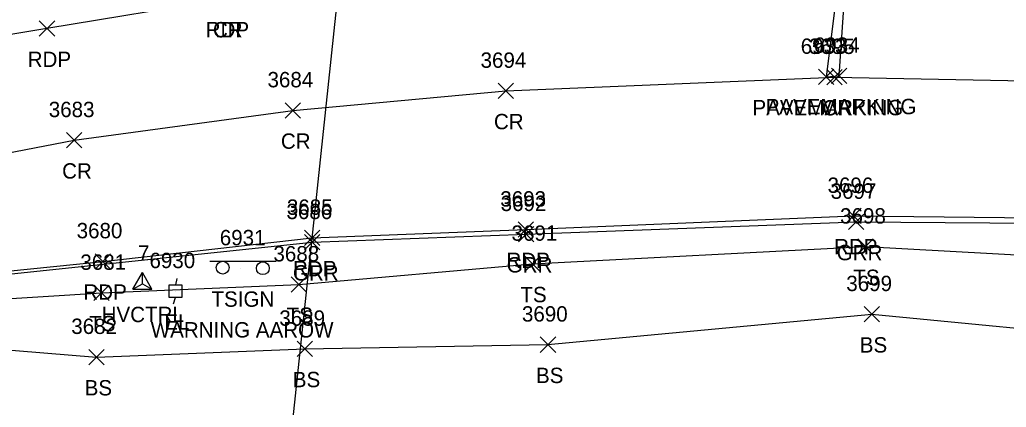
# Model space of a CAD drawing. Extents: x 1505656 to 1508446, y 700805 to 703031.
# Drawn here: x 1506576.4 to 1506704.7, y 701784.4 to 701834.8 of the extents above; entities that cross this region are included whole.
import ezdxf

# ---------------------------------------------------------------- set-up
doc = ezdxf.new("R2010")
doc.units = 0
for name, color, linetype in [('C_A', 7, 'Continuous'), ('C_I', 7, 'Continuous'), ('CPSM', 7, 'Continuous'), ('DDEFAULT', 7, 'Continuous'), ('L_A', 7, 'Continuous'), ('L_I', 7, 'Continuous'), ('L_TIC', 7, 'Continuous'), ('LELB', 7, 'Continuous'), ('P_A', 7, 'Continuous'), ('P_I', 7, 'Continuous'), ('P_TIC', 7, 'Continuous'), ('PET', 7, 'Continuous'), ('PRC', 7, 'Continuous'), ('R_A', 7, 'Continuous'), ('R_I', 7, 'Continuous'), ('R_TIC', 7, 'Continuous'), ('RGR', 7, 'Continuous'), ('S_A', 7, 'Continuous'), ('S_C', 7, 'Continuous'), ('S_I', 7, 'Continuous'), ('S_TIC', 7, 'Continuous'), ('SSGN', 7, 'Continuous'), ('STS', 7, 'Continuous'), ('U_A', 7, 'Continuous'), ('U_I', 7, 'Continuous'), ('UEPT', 7, 'Continuous')]:
    doc.layers.add(name, color=color, linetype=linetype)

msp = doc.modelspace()

# ---------------------------------------------------------------- linework, layer by layer
at = {"layer": 'CPSM'}
for p, q in [((1506591.08, 701799.76), (1506592.33, 701801.92)), ((1506593.58, 701799.76), (1506592.33, 701801.92)), ((1506592.33, 701800.48), (1506592.33, 701801.92)), ((1506591.08, 701799.76), (1506592.33, 701800.48)), ((1506592.33, 701800.48), (1506592.33, 701800.48)), ((1506592.33, 701800.48), (1506593.58, 701799.76)), ((1506591.08, 701799.76), (1506593.58, 701799.76))]:
    msp.add_line(p, q, dxfattribs=at)
at = {"layer": 'DDEFAULT'}
msp.add_lwpolyline([(1506607.79, 701743.71), (1506620.07, 701859.63)], dxfattribs=at)
at = {"layer": 'L_TIC'}
for points in [[(1506685.41, 701804.31), (1506687.41, 701806.31)], [(1506687.41, 701804.31), (1506685.41, 701806.31)], [(1506642.1, 701802.07), (1506644.1, 701804.07)], [(1506644.1, 701802.07), (1506642.1, 701804.07)], [(1506611.69, 701799.38), (1506613.69, 701801.38)], [(1506613.69, 701799.38), (1506611.69, 701801.38)], [(1506586.01, 701798.29), (1506588.01, 701800.29)], [(1506588.01, 701798.29), (1506586.01, 701800.29)], [(1506686.22, 701795.52), (1506688.22, 701797.52)], [(1506688.22, 701795.52), (1506686.22, 701797.52)], [(1506612.46, 701791.01), (1506614.46, 701793.01)], [(1506614.46, 701791.01), (1506612.46, 701793.01)], [(1506644.1, 701791.55), (1506646.1, 701793.55)], [(1506646.1, 701791.55), (1506644.1, 701793.55)], [(1506585.38, 701789.94), (1506587.38, 701791.94)], [(1506587.38, 701789.94), (1506585.38, 701791.94)]]:
    msp.add_lwpolyline(points, dxfattribs=at)
at = {"layer": 'LELB'}
for points in [[(1506551.26, 701797.2), (1506558.65, 701795.18), (1506571.81, 701798.33), (1506587.01, 701799.29), (1506612.69, 701800.38), (1506643.1, 701803.07), (1506686.41, 701805.31), (1506719.43, 701803.51), (1506758.52, 701801.61), (1506800.37, 701797.23), (1506837.5, 701789.66)], [(1506558.65, 701795.18), (1506572.61, 701792.03), (1506586.38, 701790.94), (1506613.46, 701792.01), (1506645.1, 701792.55), (1506687.22, 701796.52), (1506721.34, 701793.21), (1506758.89, 701789.89), (1506799.48, 701793.76), (1506835.55, 701784.17), (1506872.57, 701779.99)]]:
    msp.add_lwpolyline(points, dxfattribs=at)
at = {"layer": 'P_TIC'}
for points in [[(1506578.92, 701832.68), (1506580.92, 701834.68)], [(1506580.92, 701832.68), (1506578.92, 701834.68)], [(1506681.36, 701826.38), (1506683.36, 701828.38)], [(1506683.36, 701826.38), (1506681.36, 701828.38)], [(1506638.63, 701824.58), (1506640.63, 701826.58)], [(1506640.63, 701824.58), (1506638.63, 701826.58)], [(1506610.92, 701822.04), (1506612.92, 701824.04)], [(1506612.92, 701822.04), (1506610.92, 701824.04)], [(1506582.46, 701818.16), (1506584.46, 701820.16)], [(1506584.46, 701818.16), (1506582.46, 701820.16)], [(1506683.84, 701808.3), (1506685.84, 701810.3)], [(1506685.84, 701808.3), (1506683.84, 701810.3)], [(1506641.2, 701806.52), (1506643.2, 701808.52)], [(1506643.2, 701806.52), (1506641.2, 701808.52)], [(1506613.43, 701805.45), (1506615.43, 701807.45)], [(1506615.43, 701805.45), (1506613.43, 701807.45)], [(1506586.17, 701802.39), (1506588.17, 701804.39)], [(1506588.17, 701802.39), (1506586.17, 701804.39)]]:
    msp.add_lwpolyline(points, dxfattribs=at)
at = {"layer": 'PET'}
for points in [[(1506503.96, 701935.54), (1506531.72, 701909.61), (1506554.95, 701887), (1506562.54, 701879.07), (1506567.48, 701868.84), (1506568.91, 701854.51), (1506562.93, 701840.15), (1506555.32, 701831.94), (1506552.83, 701829.17), (1506534.04, 701823.97), (1506542.56, 701811.26), (1506550.99, 701798.42), (1506571.31, 701801.75), (1506587.17, 701803.39), (1506614.43, 701806.45), (1506642.2, 701807.52), (1506684.84, 701809.3), (1506720.17, 701808.92), (1506758.85, 701806.5), (1506801.05, 701801.39), (1506837.91, 701794.78)], [(1506681.03, 701845.6), (1506644.05, 701842.71), (1506621.37, 701840), (1506603.08, 701837.54), (1506579.92, 701833.68), (1506552.83, 701829.17)]]:
    msp.add_lwpolyline(points, dxfattribs=at)
at = {"layer": 'PRC'}
msp.add_lwpolyline([(1506542.56, 701811.26), (1506583.46, 701819.16), (1506611.92, 701823.04), (1506639.63, 701825.58), (1506682.36, 701827.38), (1506720.71, 701826.61), (1506759.11, 701825.09), (1506802.87, 701820.09), (1506841.69, 701813.28), (1506883.62, 701802.65), (1506939.52, 701784.02), (1506961.71, 701775.32), (1506990.86, 701762.61), (1507014.94, 701750.7), (1507047.18, 701733.31), (1507059.63, 701726.12), (1507093.71, 701705.34), (1507109.29, 701695.3), (1507149.33, 701669.46), (1507158.78, 701662.65), (1507185.01, 701645.13), (1507221.62, 701620.55), (1507265.06, 701591.23)], dxfattribs=at)
at = {"layer": 'R_TIC'}
for points in [[(1506684.18, 701807.53), (1506686.18, 701809.53)], [(1506686.18, 701807.53), (1506684.18, 701809.53)], [(1506613.43, 701804.89), (1506615.43, 701806.89)], [(1506615.43, 701804.89), (1506613.43, 701806.89)], [(1506641.25, 701805.94), (1506643.25, 701807.94)], [(1506643.25, 701805.94), (1506641.25, 701807.94)]]:
    msp.add_lwpolyline(points, dxfattribs=at)
at = {"layer": 'RGR'}
msp.add_lwpolyline([(1506551.24, 701797.84), (1506571.59, 701801.36), (1506614.43, 701805.89), (1506642.25, 701806.94), (1506685.18, 701808.53), (1506719.99, 701808.29), (1506758.76, 701805.83), (1506800.88, 701800.84), (1506837.73, 701793.83), (1506878.73, 701783.93), (1506932.12, 701767.5), (1506956.3, 701757.77), (1506981.82, 701746.54), (1507005.68, 701734.48), (1507036.84, 701717.62), (1507049.28, 701710.58), (1507081.07, 701691.67), (1507098.39, 701680.19), (1507136.76, 701655.28), (1507148.64, 701647.4), (1507175.49, 701629.55), (1507209.72, 701606.66), (1507254.7, 701574.39), (1507264.03, 701565.84)], dxfattribs=at)
at = {"layer": 'S_TIC'}
for points in [[(1506680.28, 701826.4), (1506682.28, 701828.4)], [(1506682.28, 701826.4), (1506680.28, 701828.4)], [(1506681.99, 701826.54), (1506683.99, 701828.54)], [(1506683.99, 701826.54), (1506681.99, 701828.54)]]:
    msp.add_lwpolyline(points, dxfattribs=at)
at = {"layer": 'SSGN'}
for p, q in [((1506601.12, 701803.4), (1506609.72, 701803.4)), ((1506605.15, 701802.5), (1506605.15, 701802.5))]:
    msp.add_line(p, q, dxfattribs=at)
for centre in [(1506602.78, 701802.57), (1506608, 701802.5)]:
    msp.add_circle(centre, 0.833, dxfattribs=at)
at = {"layer": 'STS'}
msp.add_lwpolyline([(1506683.55, 701845.4), (1506681.28, 701827.4), (1506682.99, 701827.54), (1506684.23, 701845.91)], dxfattribs=at)
at = {"layer": 'UEPT'}
for p, q in [((1506595.81, 701798.68), (1506595.81, 701800.35)), ((1506595.81, 701800.35), (1506597.48, 701800.35)), ((1506596.81, 701801.18), (1506596.64, 701800.35)), ((1506597.48, 701800.35), (1506597.48, 701798.68)), ((1506596.64, 701799.51), (1506596.64, 701799.51)), ((1506597.48, 701798.68), (1506595.81, 701798.68)), ((1506596.39, 701797.85), (1506596.64, 701798.68))]:
    msp.add_line(p, q, dxfattribs=at)

# ---------------------------------------------------------------- texts
at = {"layer": 'C_A'}
msp.add_text('HVCTRL', height=2, dxfattribs=at).set_placement((1506587.03, 701795.48))
at = {"layer": 'C_I'}
msp.add_text('7', height=2, dxfattribs=at).set_placement((1506591.77, 701803.48))
at = {"layer": 'L_A'}
for s, p in [('TS', (1506684.82, 701800.31)), ('TS', (1506641.51, 701798.07)), ('TS', (1506611.1, 701795.38)), ('TS', (1506585.41, 701794.29)), ('BS', (1506685.66, 701791.52)), ('BS', (1506611.9, 701787.01)), ('BS', (1506643.54, 701787.55)), ('BS', (1506584.82, 701785.94))]:
    msp.add_text(s, height=2, dxfattribs=at).set_placement(p)
at = {"layer": 'L_I'}
for s, p in [('3698', (1506683.1, 701808.31)), ('3691', (1506640.36, 701806.07)), ('3681', (1506584.26, 701802.29)), ('3688', (1506609.38, 701803.38)), ('3699', (1506683.91, 701799.52)), ('3689', (1506610.15, 701795.01)), ('3690', (1506641.71, 701795.55)), ('3682', (1506583.08, 701793.94))]:
    msp.add_text(s, height=2, dxfattribs=at).set_placement(p)
at = {"layer": 'P_A'}
for s, p in [('RDP', (1506600.57, 701832.54)), ('CR', (1506601.51, 701832.54)), ('RDP', (1506577.41, 701828.68)), ('CR', (1506680.79, 701822.38)), ('CR', (1506638.07, 701820.58)), ('CR', (1506610.35, 701818.04)), ('CR', (1506581.89, 701814.16)), ('RDP', (1506682.32, 701804.3)), ('RDP', (1506639.69, 701802.52)), ('RDP', (1506611.92, 701801.45)), ('RDP', (1506584.66, 701798.39))]:
    msp.add_text(s, height=2, dxfattribs=at).set_placement(p)
at = {"layer": 'P_I'}
for s, p in [('3695', (1506679.05, 701830.38)), ('3694', (1506636.33, 701828.58)), ('3684', (1506608.61, 701826.04)), ('3683', (1506580.15, 701822.16)), ('3696', (1506681.47, 701812.3)), ('3693', (1506638.89, 701810.52)), ('3685', (1506611.13, 701809.45)), ('3680', (1506583.78, 701806.39))]:
    msp.add_text(s, height=2, dxfattribs=at).set_placement(p)
at = {"layer": 'R_A'}
for p in [(1506682.66, 701803.53), (1506611.92, 701800.89), (1506639.73, 701801.94)]:
    msp.add_text('GRR', height=2, dxfattribs=at).set_placement(p)
at = {"layer": 'R_I'}
for s, p in [('3697', (1506681.87, 701811.53)), ('3692', (1506638.94, 701809.94)), ('3686', (1506611.07, 701808.89))]:
    msp.add_text(s, height=2, dxfattribs=at).set_placement(p)
at = {"layer": 'S_A'}
for s, p in [('PAVEMARKING', (1506671.7, 701822.4)), ('PAVEMARKING', (1506673.41, 701822.54)), ('TSIGN', (1506601.32, 701797.48))]:
    msp.add_text(s, height=2, dxfattribs=at).set_placement(p)
at = {"layer": 'S_C'}
msp.add_text('WARNING AAROW', height=2, dxfattribs=at).set_placement((1506593.42, 701793.48))
at = {"layer": 'S_I'}
for s, p in [('6934', (1506679.69, 701830.54)), ('6933', (1506677.98, 701830.4)), ('6931', (1506602.4, 701805.48))]:
    msp.add_text(s, height=2, dxfattribs=at).set_placement(p)
at = {"layer": 'U_A'}
msp.add_text('EL', height=2, dxfattribs=at).set_placement((1506595.18, 701794.51))
at = {"layer": 'U_I'}
msp.add_text('6930', height=2, dxfattribs=at).set_placement((1506593.25, 701802.51))

doc.saveas('drawing.dxf')
